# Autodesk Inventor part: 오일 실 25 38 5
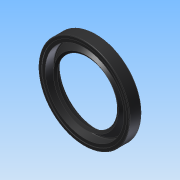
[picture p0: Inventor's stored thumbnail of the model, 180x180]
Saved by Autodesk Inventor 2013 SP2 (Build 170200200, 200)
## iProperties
Created: 2025-08
Part Number: 오일 실 25 38 5
Material: Generic
Document SubType Name: Modeling
Designer: i
Density: 1 g/cm^3
Author: i
변환 표준: STEP AP214IS
전처리기: Build: 200, Release: 2013 SP2 Update 6 - Date: Thu 07/17/2014
전송 단위: 밀리미터
불확실성: 0.01
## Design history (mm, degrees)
node "오일 실 25 38 51"
body "Solid1"
node "기준1"
